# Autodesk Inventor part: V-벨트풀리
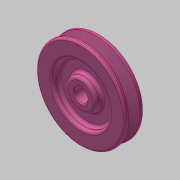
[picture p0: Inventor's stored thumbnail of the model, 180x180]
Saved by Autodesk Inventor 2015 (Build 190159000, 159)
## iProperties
Created: 2020-05
Part Number: V-벨트풀리
Material: 알루미늄 6061
Document SubType Name: Modeling
Designer: mduedu
Density: 1 g/cm^3
Appearance: 분홍색
Author: mduedu
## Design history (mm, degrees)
sketch "스케치1"
  geometry: L1 (-10, 0)-(10, 0); L2 (10, 47.5)-(-10, 47.5); L3 (-5.976, 47.5)-(-2.154, 35); L4 (-2.154, 35)-(2.154, 35); L5 (2.154, 35)-(5.976, 47.5); L6 (0, 0)-(0, 47.5); L7 (-10, 30)-(-3, 30); L8 (-3, 30)-(-3, 16); L9 (-3, 16)-(-10, 16); L10 (-10, 47.5)-(-10, 30); L11 (-10, 16)-(-10, 0); L12 (10, 30)-(3, 30); L13 (3, 30)-(3, 16); L14 (3, 16)-(10, 16); L15 (10, 0)-(10, 16); L16 (10, 30)-(10, 47.5); L17 (-4.6, 43)-(4.6, 43); 2 further points
  constraints: 34 end point, 6 parallel, 6 perpendicular, 4 point on line, 4 symmetric about line, 3 midpoint, 2 horizontal, 1 coincident, 1 collinear, 1 equal length, 1 vertical alignment
  dimensions: "d0" = 95 diameter of L2 L1; "d2" = 20 distance between parallel lines of L16 L10; "d3" = 6 distance between parallel lines of L13 L8; "d4" = 32 diameter of L14 L1; "d5" = 60 diameter of L12 L1; "d6" = 4.5 distance between parallel lines of L17 L2; "d7" = 8 distance between parallel lines of L4 L17; "d8" = 34 deg angle of L5 L3; "d9" = 9.2 distance of L17.start L17.end
revolve "회전1" sketch "스케치1" stored, may be unused: angle "d10" = 90 deg
sketch "스케치2"
  geometry: L1 (-2.5, 6.538)-(2.5, 6.538); L2 (2.5, 6.538)-(2.5, 9.3); L3 (2.5, 9.3)-(-2.5, 9.3); L4 (-2.5, 9.3)-(-2.5, 6.538); A1 r 7 centre (0, 0) between (-2.5, 6.538) and (2.5, 6.538); 1 further point
  constraints: 8 end point, 2 parallel, 2 point on circle, 1 centre point, 1 coincident, 1 horizontal, 1 perpendicular
  dimensions: "d11" = 14 diameter of A1; "d13" = 16.3 dimension on A1 L3; "d14" = 5 distance of L2.end L3.end
extrude "돌출1" cut sketch "스케치2" stored distance "d15" = 10; taper "d16" = 0 deg
chamfer "모따기1" distance "d17" = 1; stored, may be unused: second distance "d18" = 2, angle "d19" = 45 deg
fillet "모깎기1" dims "d20" = 3
fillet "모깎기2" dims "d21" = 2
fillet "모깎기3" dims "d22" = 1
fillet "모깎기4" dims "d23" = 0.5
fillet "모깎기5" dims "d24" = 3
node "솔리드1"
